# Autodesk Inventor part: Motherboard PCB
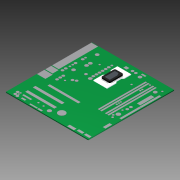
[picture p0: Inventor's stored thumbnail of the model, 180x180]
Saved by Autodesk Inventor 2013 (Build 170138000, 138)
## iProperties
Company: Autodesk Inc.
Created: 2005-11
Part Number: Motherboard PCB
Document SubType Name: Modeling
Designer: Autodesk Inc.
Density: 1 g/cm^3
Mass: 157.165 g
Surface Area: 1272.04 cm^2
Volume: 157.165 cm^3
Material: Allgemein
Title: Personal Computer
Author: Autodesk Inc.
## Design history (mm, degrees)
sketch "Sketch1"
  geometry: L1 (0, 300)-(0, -50) reference; L2 (-48, 0)-(288, 0) reference; L3 (0, 0)-(240, 0); L4 (240, 0)-(240, 250); L5 (240, 250)-(0, 250); L6 (0, 250)-(0, 0)
  constraints: 8 end point, 2 parallel, 2 point on line, 1 horizontal, 1 perpendicular
  dimensions: "d0" = 240 distance of L4.end L5.end; "d1" = 250 distance of L3.end L4.end
extrude "Extrusion1" new body sketch "Sketch1" distance "d2" = 2.5; taper "d3" = 0 deg
sketch "Sketch24"
  geometry: L1 (0, 0)-(0, 250) reference; L2 (240, 0)-(0, 0) reference; L3 (28, 36)-(113, 36); L4 (113, 36)-(113, 28); L5 (113, 28)-(28, 28); L6 (28, 28)-(28, 36)
  constraints: 8 end point, 2 parallel, 1 horizontal, 1 perpendicular
  dimensions: "d181" = 28 distance between parallel lines of L2 L5; "d182" = 28 distance between parallel lines of L1 L6; "d183" = 8 distance of L3.end L4.end; "d184" = 85 distance of L3.start L3.end
extrude "Extrusion24" cut sketch "Sketch24" distance "d185" = 0.1; taper "d186" = 0 deg
pattern_linear "Rectangular Pattern7" dims "d189" = 22
sketch "Sketch25"
  geometry: L1 (28, 58)-(113, 58) reference; L2 (0, 0)-(0, 250) reference; L3 (44.8, 83)-(134.8, 83); L4 (134.8, 83)-(134.8, 76); L5 (134.8, 76)-(44.8, 76); L6 (44.8, 76)-(44.8, 83)
  constraints: 8 end point, 2 parallel, 1 horizontal, 1 perpendicular
  dimensions: "d190" = 18 distance between parallel lines of L1 L5; "d191" = 44.8 distance between parallel lines of L2 L6; "d192" = 90 distance of L3.start L3.end; "d193" = 7 distance of L3.end L4.end
extrude "Extrusion25" cut sketch "Sketch25" distance "d194" = 0.1; taper "d195" = 0 deg
sketch "Sketch11"
  geometry: L1 (240, 250)-(240, 0) reference; L2 (0, 250)-(240, 250) reference; L3 (205, 230)-(210, 230); L4 (210, 230)-(210, 90); L5 (210, 90)-(205, 90); L6 (205, 90)-(205, 230)
  constraints: 8 end point, 2 parallel, 1 horizontal, 1 perpendicular
  dimensions: "d79" = 30 distance between parallel lines of L1 L4; "d80" = 140 distance of L3.end L4.end; "d81" = 5 distance of L3.start L3.end; "d82" = 20 distance between parallel lines of L3 L2
extrude "Extrusion11" cut sketch "Sketch11" distance "d83" = 0.5; taper "d84" = 0 deg
pattern_linear "Rectangular Pattern4" dims "d87" = 7
sketch "Sketch12"
  geometry: L1 (0, 0)-(0, 250) reference; L2 (0, 250)-(240, 250) reference; L3 (100, 225)-(140, 225); L4 (140, 225)-(140, 155); L5 (140, 155)-(100, 155); L6 (100, 155)-(100, 225)
  constraints: 8 end point, 2 parallel, 1 horizontal, 1 perpendicular
  dimensions: "d88" = 70 distance of L5.end L3.start; "d90" = 40 distance of L3.start L3.end; "d464" = 100 distance from line of L3.start L1; "d465" = 25 distance from line of L3.start L2
extrude "Extrusion12" join sketch "Sketch12" distance "d92" = 2; taper "d93" = 0 deg
sketch "Sketch22"
  geometry: L1 (140, 225)-(140, 155) reference; L2 (100, 225)-(140, 225) reference; L3 (100, 155)-(100, 225) reference; L4 (140, 155)-(100, 155) reference; L5 (140, 205)-(136, 201); L6 (136, 201)-(136, 186); L7 (136, 186)-(140, 182); L8 (120, 225)-(120, 155); L9 (100, 205)-(104, 201); L10 (104, 201)-(104, 186); L11 (104, 186)-(100, 182); L12 (100, 205)-(100, 182); L13 (100, 205)-(100, 182)
  constraints: 18 end point, 4 point on line, 4 symmetric about line, 3 perpendicular, 2 midpoint, 1 collinear, 1 parallel
  dimensions: "d176" = 15 distance of L5.end L6.end; "d177" = 4 distance between parallel lines of L1 L6; "d178" = 20 distance from line of L5.start L2
extrude "Extrusion23" cut sketch "Sketch22" stored distance "d179" = 10; taper "d180" = 0 deg
workplane "Work Plane1"
sketch "Sketch14"
  geometry: L1 (120, 225)-(120, 155); L2 (107.5, 210)-(132.5, 210); L3 (132.5, 210)-(132.5, 170); L4 (132.5, 170)-(107.5, 170); L5 (107.5, 170)-(107.5, 210); L6 (100, 225)-(140, 225) reference; L7 (140, 155)-(100, 155) reference; L8 (120, 190)-(125.402, 190)
  constraints: 12 end point, 3 midpoint, 3 parallel, 2 perpendicular, 1 horizontal, 2 other
  dimensions: "d97" = 25 distance of L2.start L2.end; "d98" = 40 distance of L4.end L2.start
extrude "Extrusion13" join sketch "Sketch14" distance "d99" = 4; taper "d100" = 0 deg
sketch "Sketch15"
  geometry: L1 (132.5, 210)-(132.5, 170) reference; L2 (107.5, 210)-(132.5, 210) reference; L3 (107.5, 170)-(107.5, 210) reference; L4 (132.5, 170)-(107.5, 170) reference; L5 (127.5, 205)-(127.5, 175); L6 (127.5, 175)-(112.5, 175); L7 (112.5, 175)-(112.5, 205); L8 (112.5, 205)-(127.5, 205); L9 (123.5, 205)-(127.5, 197)
  constraints: 10 end point, 2 point on line, 3 other
  dimensions: "d101" = 5 distance between parallel lines of L2 L8; "d102" = 4 distance from line of L5 L9.start; "d103" = 8 distance from line of L9.end L8
extrude "Extrusion14" cut sketch "Sketch15" distance "d104" = 0.1; taper "d105" = 0 deg
workplane "Work Plane2"
sketch "Sketch16"
  geometry: L1 (132.5, 208)-(132.5, 172) reference; L2 (132.5, 207)-(133.5, 207); L3 (133.5, 207)-(133.5, 206.75); L4 (133.5, 205.5)-(132.5, 205.5); L5 (132.5, 205.5)-(132.5, 207); L6 (133.6, 206.65)-(135, 206.65); L7 (135, 205.85)-(133.6, 205.85); L8 (132.5, 206.25)-(131.249, 206.25); L9 (109.5, 210)-(130.5, 210) reference; L10 (133.5, 205.5)-(133.5, 205.75); L11 (135, 206.65)-(135, 205.85); A1 r 0.1 centre (133.6, 206.75) between (133.5, 206.75) and (133.6, 206.65); A2 r 0.1 centre (133.6, 205.75) between (133.6, 205.85) and (133.5, 205.75)
  constraints: 18 end point, 4 parallel, 4 point on circle, 4 tangent, 2 centre point, 2 horizontal, 2 perpendicular, 2 point on line, 1 midpoint, 1 other
  dimensions: "d110" = 1 distance of L2.start L2.end; "d112" = 1.5 distance between parallel lines of L4 L2; "d117" = 0.1 radius of A1; "d118" = 0.1 radius of A2; "d128" = 1.5 distance between parallel lines of L3 L11; "d129" = 0.8 distance of L6.end L7.start; "d141" = 3 distance between parallel lines of L2 L9
extrude "Extrusion18" join sketch "Sketch16" stored distance "d130" = 0.1; taper "d131" = 0 deg
sketch "Sketch18"
  geometry: L1 (0, 0)-(0, 0.5) reference; L2 (0, 0)-(1, 0) reference; L3 (2.5, 0)-(2.5, 1) reference; L4 (0, 0.2)-(2.3, 0.2); L5 (2.3, 0.2)-(2.3, 1); L6 (2.3, 1)-(0, 1); L7 (0, 1)-(0, 0.2); L8 (-32.5, 1)-(7.5, 1) reference
  constraints: 8 end point, 2 parallel, 1 collinear, 1 horizontal, 1 perpendicular, 1 point on line
  dimensions: "d132" = 0.2 distance between parallel lines of L3 L5 (derived); "d133" = 0.2 distance between parallel lines of L2 L4
extrude "Extrusion19" cut sketch "Sketch18" stored distance "d134" = 0.1; taper "d135" = 0 deg
fillet "Fillet1" dims "d136" = 0.3, "d137" = 0.5
workplane "Work Plane4"
workplane "Work Plane5"
mirror "Mirror1"
sketch "Sketch19"
  geometry: L1 (132.5, 170)-(107.5, 170) reference; L2 (128, 170)-(129.5, 170); L3 (129.5, 170)-(129.5, 169); L4 (128.25, 169)-(128, 169); L5 (128, 169)-(128, 170); L6 (129.15, 168.9)-(129.15, 167.5); L7 (129.15, 167.5)-(128.35, 167.5); L8 (128.35, 167.5)-(128.35, 168.9); L9 (132.5, 210)-(132.5, 170) reference; L10 (129.5, 169)-(129.25, 169); L11 (128.75, 167.5)-(128.75, 168.31); A1 r 0.1 centre (128.25, 168.9) between (128.35, 168.9) and (128.25, 169); A2 r 0.1 centre (129.25, 168.9) between (129.25, 169) and (129.15, 168.9)
  constraints: 18 end point, 4 point on circle, 4 tangent, 3 parallel, 3 perpendicular, 2 centre point, 2 point on line, 1 horizontal, 1 midpoint, 2 other
  dimensions: "d143" = 0.1 radius of A1; "d144" = 0.1 radius of A2; "d145" = 3 distance between parallel lines of L9 L3; "d146" = 1.5 distance between parallel lines of L3 L5; "d147" = 0.8 distance between parallel lines of L6 L8; "d148" = 1 distance of L4.end L2.start; "d149" = 1.5 distance between parallel lines of L4 L7
extrude "Extrusion20" join sketch "Sketch19" stored distance "d150" = 10; taper "d151" = 0 deg
sketch "Sketch20"
  geometry: L1 (0, -1.5)-(1, -1.5) reference; L2 (1, 1)-(0.2, 1); L3 (0.2, 1)-(0.2, -1.3); L4 (0.2, -1.3)-(1, -1.3); L5 (1, -1.3)-(1, 1); L6 (0, -0.1)-(0, -1.5) reference
  constraints: 8 end point, 2 parallel, 1 horizontal, 1 perpendicular
  dimensions: "d153" = 0.2 distance between parallel lines of L6 L3; "d154" = 0.2 distance between parallel lines of L1 L4 (derived)
extrude "Extrusion21" cut sketch "Sketch20" stored distance "d155" = 10; taper "d156" = 0 deg
fillet "Fillet2" dims "d157" = 0.3, "d158" = 0.5
pattern_linear "Rectangular Pattern6" dims "d161" = 17.5
mirror "Mirror2"
chamfer "Chamfer2" distance "d162" = 2; stored, may be unused: second distance "d163" = 2, angle "d164" = 45 deg
sketch "Sketch21"
  geometry: L1 (0, 0)-(0, 250) reference; L2 (240, 0)-(0, 0) reference; L3 (0, 90)-(25, 90); L4 (25, 90)-(25, 112); L5 (25, 112)-(0, 112); L6 (0, 112)-(0, 90); L7 (0, 114)-(22, 114); L8 (22, 114)-(22, 132); L9 (22, 132)-(0, 132); L10 (0, 132)-(0, 114); L11 (0, 134)-(20, 134); L12 (20, 134)-(20, 249); L13 (20, 249)-(0, 249); L14 (0, 249)-(0, 134)
  constraints: 24 end point, 6 parallel, 3 horizontal, 3 perpendicular, 3 point on line
  dimensions: "d165" = 90 distance between parallel lines of L2 L3; "d166" = 22 distance of L3.end L4.end; "d167" = 18 distance of L7.end L8.end; "d168" = 2 distance between parallel lines of L7 L5; "d169" = 25 distance of L3.start L3.end; "d170" = 22 distance of L8.end L9.end; "d171" = 2 distance between parallel lines of L9 L11; "d172" = 115 distance of L11.end L12.end; "d173" = 20 distance between parallel lines of L1 L12
extrude "Extrusion22" cut sketch "Sketch21" distance "d174" = 0.5; taper "d175" = 0 deg
sketch "Sketch26"
  geometry: L1 (0, 0)-(0, 90) reference; L2 (240, 0)-(0, 0) reference; L3 (240, 250)-(240, 0) reference; L4 (32, 20)-(57, 20); L5 (57, 20)-(57, 15); L6 (57, 15)-(32, 15); L7 (32, 15)-(32, 20); L8 (38, 10)-(50, 10); L9 (50, 10)-(50, 5); L10 (50, 5)-(38, 5); L11 (38, 5)-(38, 10); L12 (65, 6.5)-(87, 6.5); L13 (87, 6.5)-(87, 2.5); L14 (87, 2.5)-(65, 2.5); L15 (65, 2.5)-(65, 6.5); L16 (89, 7)-(101, 7); L17 (101, 7)-(101, 2); L18 (101, 2)-(89, 2); L19 (89, 2)-(89, 7); L20 (176, 10)-(196, 10); L21 (196, 10)-(196, 2); L22 (196, 2)-(176, 2); L23 (176, 2)-(176, 10); L24 (201, 12)-(217, 12); L25 (217, 12)-(217, 5); L26 (217, 5)-(201, 5); L27 (201, 5)-(201, 12); L28 (222, 12)-(238, 12); L29 (238, 12)-(238, 5); L30 (238, 5)-(222, 5); L31 (222, 5)-(222, 12); L32 (230, 72)-(238, 72); L33 (238, 72)-(238, 52); L34 (238, 52)-(230, 52); L35 (230, 52)-(230, 72)
  constraints: 64 end point, 16 parallel, 8 horizontal, 8 perpendicular
  dimensions: "d196" = 12 distance of L9.end L10.end; "d197" = 5 distance of L10.end L8.start; "d198" = 22 distance of L12.start L12.end; "d199" = 4 distance of L14.end L12.start; "d200" = 20 distance of L21.end L22.end; "d201" = 8 distance of L22.end L20.start; "d202" = 16 distance of L25.end L26.end; "d203" = 16 distance of L29.end L30.end; "d204" = 7 distance of L26.end L24.start; "d205" = 7 distance of L30.end L28.start; "d206" = 25 distance of L4.start L4.end; "d207" = 5 distance of L6.end L4.start; "d208" = 32 distance between parallel lines of L1 L7; "d209" = 15 distance between parallel lines of L2 L6; "d210" = 38 distance between parallel lines of L1 L11; "d211" = 5 distance between parallel lines of L2 L10; "d212" = 2.5 distance between parallel lines of L2 L14; "d213" = 65 distance between parallel lines of L1 L15; "d214" = 2 distance between parallel lines of L19 L13; "d215" = 12 distance of L17.end L18.end; "d216" = 5 distance of L16.end L17.end; "d217" = 2 distance between parallel lines of L2 L18; "d218" = 2 distance between parallel lines of L3 L29; "d219" = 5 distance between parallel lines of L25 L31; "d220" = 5 distance between parallel lines of L21 L27; "d221" = 5 distance between parallel lines of L2 L30; "d222" = 5 distance between parallel lines of L2 L26; "d223" = 2 distance between parallel lines of L2 L22; "d226" = 20 distance of L34.end L32.start; "d227" = 8 distance of L32.start L32.end; "d228" = 2 distance between parallel lines of L3 L33; "d229" = 52 distance between parallel lines of L2 L34
extrude "Extrusion26" cut sketch "Sketch26" distance "d224" = 0.1; taper "d225" = 0 deg
sketch "Sketch27"
  geometry: L1 (240, 250)-(240, 0) reference; L2 (0, 250)-(240, 250) reference; L3 (232, 156.5)-(238, 156.5); L4 (238, 156.5)-(238, 98.5); L5 (238, 98.5)-(232, 98.5); L6 (232, 98.5)-(232, 156.5); L7 (232, 157)-(238, 157); L8 (238, 157)-(238, 215); L9 (238, 215)-(232, 215); L10 (232, 215)-(232, 157); L11 (230, 203)-(220, 203); L12 (220, 203)-(220, 161.366); L13 (220, 161.366)-(230, 161.366); L14 (230, 161.366)-(230, 203); L15 (153, 245)-(165, 245); L16 (165, 245)-(165, 240); L17 (165, 240)-(153, 240); L18 (153, 240)-(153, 245); L19 (110, 240)-(120, 240); L20 (120, 240)-(120, 231.818); L21 (120, 231.818)-(110, 231.818); L22 (110, 231.818)-(110, 240)
  constraints: 40 end point, 10 parallel, 5 horizontal, 5 perpendicular, 3 collinear
  dimensions: "d230" = 41.634 distance of L11.end L12.end; "d231" = 10 distance of L11.start L11.end; "d232" = 58 distance of L7.end L8.end; "d233" = 6 distance of L8.end L9.end; "d234" = 2 distance between parallel lines of L1 L8; "d235" = 35 distance between parallel lines of L9 L2; "d236" = 0.5 distance between parallel lines of L3 L7; "d237" = 2 distance between parallel lines of L10 L14; "d238" = 12 distance between parallel lines of L9 L11; "d239" = 12 distance of L16.end L17.end; "d240" = 5 distance of L17.end L15.start; "d241" = 5 distance between parallel lines of L2 L15; "d242" = 75 distance between parallel lines of L1 L16; "d466" = 120 distance between parallel lines of L20 L1; "d467" = 10 distance of L19.start L19.end; "d468" = 8.182 distance of L19.end L20.end; "d469" = 10 distance between parallel lines of L2 L19
extrude "Extrusion27" cut sketch "Sketch27" distance "d243" = 0.1; taper "d244" = 0 deg
sketch "Sketch36"
  geometry: L1 (240, 250)-(240, 0) reference; L2 (0, 250)-(240, 250) reference; C1 r 5 at (39.693, 226.244); C2 r 3 at (30.354, 201.669); C3 r 4 at (30.354, 193.555); C4 r 5 at (51.48, 194.437); C5 r 5 at (51.48, 183.487); C6 r 2.5 at (68.317, 204.801); C7 r 3 at (88.441, 220.311); C8 r 4 at (88.441, 211.357); C9 r 4 at (88.441, 202.296); C10 r 4 at (88.441, 193.296); C11 r 4 at (88.441, 184.296); C12 r 4 at (88.441, 175.296); C13 r 4 at (88.441, 166.296); C14 r 5 at (89.861, 155.993); C15 r 4 at (72.413, 160.822); C16 r 4 at (29.419, 173.441); C17 r 3 at (29.419, 165.341); C18 r 3 at (29.419, 156.929); C19 r 4 at (28.642, 145.799); C20 r 4 at (28.642, 136.351); C21 r 5 at (43.559, 153.556); C22 r 4 at (75.497, 130.56); C23 r 4 at (67.668, 126.227); C24 r 2.5 at (57.87, 114.288); C25 r 4 at (43.559, 123.633); C26 r 4 at (43.559, 114.647); C27 r 4 at (43.559, 105.419); C28 r 4 at (17.889, 16.27); C29 r 2.5 at (24.682, 17.947); C30 r 2.5 at (24.77, 12.135); C31 r 4 at (19.492, 7.72); C32 r 4 at (27.509, 5.76); C33 r 2.5 at (75.356, 19.392); C34 r 2.5 at (91.255, 18.424); C35 r 5.5 at (111.602, 15.05); C36 r 10 at (135.164, 27.552); C37 r 4 at (132.524, 236.483); C38 r 4 at (142.299, 236.173); C39 r 5 at (158.643, 232.04); C40 r 2.5 at (165.116, 201.027); C41 r 2.5 at (193.533, 226.307); C42 r 2.5 at (193.533, 204.132); C43 r 2.5 at (193.533, 198.206); C44 r 5 at (218.98, 216.282); C45 r 2.5 at (227.388, 228.53); C46 r 4 at (221.111, 143.172); C47 r 2.5 at (193.533, 141.29); C48 r 2.5 at (193.533, 135.626); C49 r 2.5 at (193.533, 129.546); C50 r 2.5 at (216.575, 123.129); C51 r 6 at (220.919, 106.847); C52 r 3 at (215.21, 97.535); C53 r 3 at (220.104, 90.832); C54 r 4 at (221.111, 132.42); 1 further point
  constraints: 54 centre point, 46 equal radius, 20 vertical alignment
  dimensions: "d327" = 10 diameter of C1; "d328" = 11 diameter of C35; "d329" = 6 diameter of C2; "d330" = 8 diameter of C3; "d331" = 8 diameter of C16; "d344" = 5 diameter of C6; "d360" = 12 diameter of C51; "d366" = 20 diameter of C36; "d374" = 12.61189 distance from line of C45.centre L1; "d375" = 21.02017 distance from line of C44.centre L1; "d376" = 18.88945 distance from line of C46.centre L1; "d377" = 23.42478 distance from line of C50.centre L1; "d378" = 19.08063 distance from line of C51.centre L1; "d379" = 24.78985 distance from line of C52.centre L1; "d380" = 19.89556 distance from line of C53.centre L1; "d381" = 46.46721 distance from line of C41.centre L1; "d382" = 74.88404 distance from line of C40.centre L1; "d383" = 81.35703 distance from line of C39.centre L1; "d384" = 97.70105 distance from line of C38.centre L1; "d385" = 107.47604 distance from line of C37.centre L1; "d386" = 104.83585 distance from line of C36.centre L1; "d387" = 128.39753 distance from line of C35.centre L1; "d388" = 148.74514 distance from line of C34.centre L1; "d389" = 164.64404 distance from line of C33.centre L1; "d390" = 212.49135 distance from line of C32.centre L1; "d391" = 215.22993 distance from line of C30.centre L1; "d392" = 215.31763 distance from line of C29.centre L1; "d393" = 220.50772 distance from line of C31.centre L1; "d394" = 222.111 distance from line of C28.centre L1; "d395" = 151.55906 distance from line of C7.centre L1; "d396" = 150.13946 distance from line of C14.centre L1; "d397" = 164.50333 distance from line of C22.centre L1; "d398" = 172.33172 distance from line of C23.centre L1; "d399" = 182.13003 distance from line of C24.centre L1; "d400" = 196.44111 distance from line of C27.centre L1; "d401" = 167.58723 distance from line of C15.centre L1; "d402" = 171.68335 distance from line of C6.centre L1; "d403" = 188.51975 distance from line of C4.centre L1; "d404" = 200.30731 distance from line of C1.centre L1; "d405" = 209.64574 distance from line of C2.centre L1; "d406" = 211.35795 distance from line of C20.centre L1; "d407" = 210.58092 distance from line of L1 C16.centre; "d408" = 21.46977 distance from line of C45.centre L2; "d409" = 13.82734 distance from line of C38.centre L2; "d410" = 17.96034 distance from line of C39.centre L2; "d411" = 23.69255 distance from line of C41.centre L2; "d412" = 33.71767 distance from line of C44.centre L2; "d413" = 45.86803 distance from line of C42.centre L2; "d414" = 48.97254 distance from line of C40.centre L2; "d415" = 51.79364 distance from line of C43.centre L2; "d416" = 106.82812 distance from line of C46.centre L2; "d417" = 108.71014 distance from line of C47.centre L2; "d418" = 114.37401 distance from line of C48.centre L2; "d419" = 120.45358 distance from line of C49.centre L2; "d420" = 126.87111 distance from line of C50.centre L2; "d421" = 143.15271 distance from line of C51.centre L2; "d422" = 152.46515 distance from line of C52.centre L2; "d423" = 159.1682 distance from line of C53.centre L2; "d424" = 222.44781 distance from line of C36.centre L2; "d425" = 234.94993 distance from line of C35.centre L2; "d426" = 23.75589 distance from line of C1.centre L2; "d427" = 29.68851 distance from line of C7.centre L2; "d428" = 38.64292 distance from line of C8.centre L2; "d429" = 45.19919 distance from line of C6.centre L2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
extrude "Extrusion35" join sketch "Sketch36" distance "d461" = 0.5; taper "d462" = 0 deg
body "Solid1"
pattern_linear "Rectangular Pattern5" dims "d140" = 32.5
other parameters: "d96" = 0.5, "d109" = 0.5
